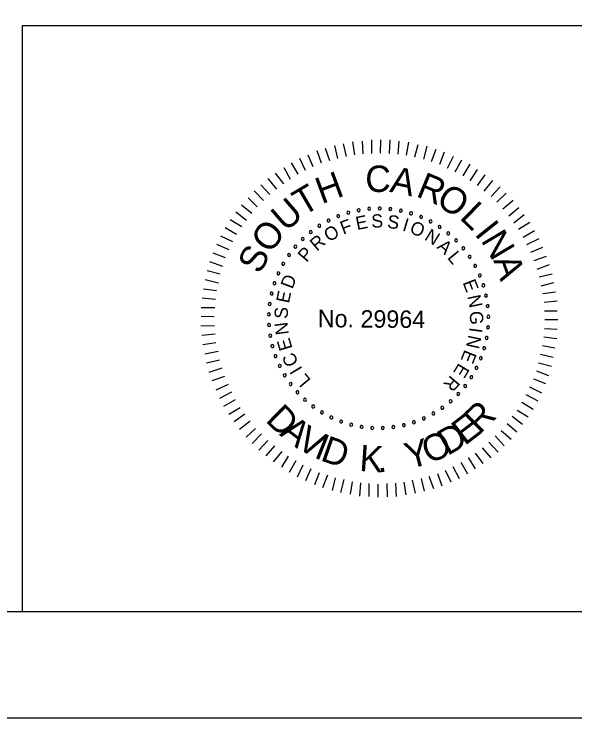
# Model space of a CAD drawing. Extents: x -50.5 to -14.4, y -5.1 to 16.9.
# Drawn here: x -27.924 to -25.289, y -5.066 to -1.762 of the extents above; entities that cross this region are included whole.
import ezdxf

# ---------------------------------------------------------------- set-up
doc = ezdxf.new("R2010")
doc.units = 0
for name, color, linetype in [('BR_BORDER LINES', 7, 'Continuous'), ('BR_TEXT', 7, 'Continuous'), ('Level 31', 7, 'Continuous')]:
    doc.layers.add(name, color=color, linetype=linetype)

msp = doc.modelspace()

# ---------------------------------------------------------------- linework, layer by layer
at = {"layer": 'BR_BORDER LINES'}
for p, q in [((-27.8847, -1.8161), (-22.5195, -1.8161)), ((-27.8847, -4.5661), (-27.8847, -1.8161)), ((-48.6853, -4.5662), (-15.0192, -4.5662))]:
    msp.add_line(p, q, dxfattribs=at)
at = {"layer": 'BR_TEXT'}
for p, q in [((-26.3625, -2.4304), (-26.3767, -2.3711)), ((-26.323, -2.423), (-26.332, -2.362)), ((-26.2835, -2.419), (-26.2873, -2.3581)), ((-26.244, -2.4168), (-26.2435, -2.3524)), ((-26.202, -2.4146), (-26.2015, -2.3528)), ((-26.1599, -2.4175), (-26.1577, -2.3531)), ((-26.1196, -2.4204), (-26.1148, -2.3595)), ((-26.081, -2.425), (-26.0702, -2.3642)), ((-26.0408, -2.4331), (-26.0265, -2.374)), ((-26.4796, -2.4629), (-26.5005, -2.4044)), ((-26.44, -2.4504), (-26.4618, -2.3927)), ((-26.4038, -2.4404), (-26.4171, -2.3793)), ((-25.9997, -2.4437), (-25.9837, -2.3829)), ((-25.9629, -2.4543), (-25.9409, -2.397)), ((-25.9235, -2.4675), (-25.9015, -2.4093)), ((-26.5553, -2.4966), (-26.5815, -2.4406)), ((-26.5183, -2.4798), (-26.5419, -2.4238)), ((-25.8876, -2.485), (-25.8597, -2.4294)), ((-26.5898, -2.5144), (-26.6202, -2.46)), ((-25.8517, -2.5024), (-25.8203, -2.4469)), ((-25.8141, -2.5208), (-25.7819, -2.467)), ((-26.6562, -2.5593), (-26.6953, -2.5083)), ((-26.6252, -2.5381), (-26.6556, -2.4838)), ((-25.7808, -2.5451), (-25.7469, -2.4913)), ((-26.6899, -2.5847), (-26.7299, -2.5346)), ((-25.7475, -2.5668), (-25.711, -2.5165)), ((-25.7151, -2.5928), (-25.6744, -2.5434)), ((-26.7228, -2.6094), (-26.7644, -2.5644)), ((-25.6836, -2.618), (-25.6403, -2.5737)), ((-26.7522, -2.6366), (-26.7964, -2.5925)), ((-25.6555, -2.6456), (-25.6122, -2.6022)), ((-26.7816, -2.6673), (-26.825, -2.6248)), ((-25.6274, -2.6768), (-25.5799, -2.6351)), ((-26.8068, -2.6988), (-26.8562, -2.6598)), ((-25.6002, -2.7088), (-25.5536, -2.6705)), ((-26.8328, -2.732), (-26.8822, -2.6922)), ((-25.5765, -2.7424), (-25.5272, -2.7033)), ((-26.8545, -2.761), (-26.9083, -2.728)), ((-25.5544, -2.7718), (-25.5018, -2.7396)), ((-26.8788, -2.7977), (-26.9326, -2.7656)), ((-26.8963, -2.8319), (-26.9526, -2.804)), ((-25.5324, -2.8089), (-25.4789, -2.7776)), ((-25.5147, -2.8433), (-25.4569, -2.8164)), ((-26.9137, -2.8687), (-26.971, -2.8433)), ((-25.4969, -2.8804), (-25.4401, -2.856)), ((-26.9312, -2.9072), (-26.9894, -2.8852)), ((-25.4801, -2.9192), (-25.4233, -2.8982)), ((-26.9435, -2.9474), (-27.0051, -2.9246)), ((-25.4667, -2.9596), (-25.409, -2.9378)), ((-26.9558, -2.9833), (-27.0167, -2.9682)), ((-25.4567, -2.9957), (-25.3965, -2.9816)), ((-26.9631, -3.0253), (-27.0256, -3.0094)), ((-25.4485, -3.0378), (-25.3882, -3.0229)), ((-26.9736, -3.0613), (-27.0345, -3.0531)), ((-25.4402, -3.074), (-25.3809, -3.0667)), ((-26.9783, -3.1024), (-27.04, -3.0951)), ((-25.4337, -3.1152), (-25.3727, -3.1088)), ((-26.9812, -3.1419), (-27.0455, -3.1414)), ((-25.4323, -3.1547), (-25.3722, -3.1552)), ((-26.9833, -3.183), (-27.0459, -3.1825)), ((-25.43, -3.1959), (-25.3691, -3.1964)), ((-26.9819, -3.226), (-27.0462, -3.2272)), ((-26.9796, -3.2646), (-27.0415, -3.2718)), ((-25.433, -3.2388), (-25.3729, -3.241)), ((-25.435, -3.2774), (-25.3741, -3.2856)), ((-26.9757, -3.3058), (-27.0367, -3.3148)), ((-25.4422, -3.3185), (-25.3831, -3.3284)), ((-26.9657, -3.3454), (-27.0284, -3.3586)), ((-25.4511, -3.3579), (-25.3911, -3.3721)), ((-26.9592, -3.3875), (-27.0202, -3.4016)), ((-25.46, -3.3999), (-25.4001, -3.415)), ((-26.9475, -3.4245), (-27.0094, -3.4454)), ((-26.9358, -3.4632), (-26.9943, -3.4842)), ((-25.4706, -3.4367), (-25.4133, -3.4586)), ((-26.9189, -3.5003), (-26.9766, -3.5272)), ((-25.4847, -3.4752), (-25.4282, -3.4971)), ((-25.5022, -3.512), (-25.4457, -3.5399)), ((-26.9021, -3.5364), (-26.9589, -3.566)), ((-25.5205, -3.5479), (-25.4632, -3.5784)), ((-26.8852, -3.5735), (-26.9395, -3.6048)), ((-25.5388, -3.5846), (-25.4859, -3.6168)), ((-26.8615, -3.6106), (-26.9158, -3.6419)), ((-25.5614, -3.6213), (-25.5093, -3.6535)), ((-26.8403, -3.6399), (-26.8903, -3.6764)), ((-25.584, -3.6503), (-25.5353, -3.6876)), ((-26.8148, -3.6736), (-26.8649, -3.7127)), ((-25.6083, -3.6836), (-25.5623, -3.7234)), ((-26.7902, -3.7073), (-26.8343, -3.7481)), ((-26.7612, -3.7333), (-26.8062, -3.7784)), ((-25.636, -3.7168), (-25.5891, -3.7584)), ((-26.7323, -3.7636), (-26.7747, -3.8095)), ((-25.6645, -3.7424), (-25.622, -3.7882)), ((-26.6999, -3.7895), (-26.7406, -3.8364)), ((-25.7251, -3.7976), (-25.6851, -3.8452)), ((-25.6931, -3.7721), (-25.6506, -3.8188)), ((-26.6666, -3.8156), (-26.7065, -3.8633)), ((-25.7579, -3.8231), (-25.7222, -3.8714)), ((-26.6359, -3.8373), (-26.6672, -3.8894)), ((-26.6009, -3.8599), (-26.6322, -3.9137)), ((-25.7915, -3.8443), (-25.7585, -3.8969)), ((-26.5668, -3.8799), (-26.5938, -3.9355)), ((-26.53, -3.8974), (-26.5545, -3.953)), ((-25.8631, -3.8857), (-25.8327, -3.9418)), ((-25.8252, -3.8663), (-25.7939, -3.9206)), ((-26.4915, -3.9149), (-26.5134, -3.9713)), ((-26.4522, -3.9272), (-26.475, -3.9854)), ((-25.9751, -3.9311), (-25.9541, -3.9897)), ((-25.9355, -3.9194), (-25.9145, -3.9763)), ((-25.8993, -3.9026), (-25.8723, -3.9586)), ((-26.4162, -3.9395), (-26.4304, -3.9986)), ((-26.3751, -3.9467), (-26.3902, -4.0084)), ((-26.3357, -3.9582), (-26.3456, -4.0165)), ((-26.2963, -3.9628), (-26.3011, -4.0246)), ((-26.1324, -3.9642), (-26.1286, -4.026)), ((-26.0937, -3.9602), (-26.0839, -4.0186)), ((-26.0533, -3.9494), (-26.0401, -4.0113)), ((-26.0121, -3.9429), (-25.9971, -4.0022)), ((-26.2568, -3.9657), (-26.2573, -4.0275)), ((-26.2148, -3.9686), (-26.2153, -4.0296)), ((-26.1727, -3.9664), (-26.1715, -4.0282))]:
    msp.add_line(p, q, dxfattribs=at)
for centre, start, end in [((-26.256, -2.6764), 5.0653, 185.0653), ((-26.256, -2.6764), 185.0653, 5.0653), ((-26.2062, -2.6745), 359.5268, 179.5268), ((-26.2062, -2.6745), 179.5268, 359.5268), ((-26.1565, -2.6774), 353.9884, 173.9884), ((-26.4011, -2.7106), 21.6807, 201.6807), ((-26.4011, -2.7106), 201.6807, 21.6807), ((-26.3539, -2.6945), 16.1422, 196.1422), ((-26.3539, -2.6945), 196.1422, 16.1422), ((-26.3054, -2.6831), 10.6038, 190.6038), ((-26.3054, -2.6831), 190.6038, 10.6038), ((-26.1565, -2.6774), 173.9884, 353.9884), ((-26.1073, -2.6851), 168.4499, 348.4499), ((-26.1073, -2.6851), 348.4499, 168.4499), ((-26.059, -2.6976), 162.9114, 342.9114), ((-26.059, -2.6976), 342.9114, 162.9114), ((-26.0122, -2.7146), 337.373, 157.373), ((-26.4465, -2.7311), 27.2191, 207.2191), ((-26.4465, -2.7311), 207.2191, 27.2191), ((-26.0122, -2.7146), 157.373, 337.373), ((-25.9672, -2.736), 151.8345, 331.8345), ((-25.9672, -2.736), 331.8345, 151.8345), ((-26.4897, -2.7559), 32.7576, 212.7576), ((-26.4897, -2.7559), 212.7576, 32.7576), ((-25.9245, -2.7617), 146.2961, 326.2961), ((-25.9245, -2.7617), 326.2961, 146.2961), ((-26.5303, -2.7848), 38.2961, 218.2961), ((-26.5303, -2.7848), 218.2961, 38.2961), ((-25.8845, -2.7914), 140.7576, 320.7576), ((-25.8845, -2.7914), 320.7576, 140.7576), ((-26.568, -2.8175), 43.8345, 223.8345), ((-26.568, -2.8175), 223.8345, 43.8345), ((-25.8475, -2.8249), 135.2191, 315.2191), ((-25.8475, -2.8249), 315.2191, 135.2191), ((-26.6023, -2.8536), 49.373, 229.373), ((-26.6023, -2.8536), 229.373, 49.373), ((-25.814, -2.8617), 129.6807, 309.6807), ((-25.814, -2.8617), 309.6807, 129.6807), ((-26.6329, -2.8929), 54.9114, 234.9114), ((-26.6329, -2.8929), 234.9114, 54.9114), ((-25.7841, -2.9016), 124.1422, 304.1422), ((-25.7841, -2.9016), 304.1422, 124.1422), ((-26.6596, -2.935), 60.4499, 240.4499), ((-26.6596, -2.935), 240.4499, 60.4499), ((-25.7583, -2.9442), 118.6038, 298.6038), ((-25.7583, -2.9442), 298.6038, 118.6038), ((-26.6822, -2.9794), 65.9884, 245.9884), ((-26.6822, -2.9794), 245.9884, 65.9884), ((-25.7366, -2.9891), 113.0653, 293.0653), ((-25.7366, -2.9891), 293.0653, 113.0653), ((-26.7003, -3.0258), 71.5268, 251.5268), ((-26.7003, -3.0258), 251.5268, 71.5268), ((-25.7195, -3.0359), 107.5268, 287.5268), ((-25.7195, -3.0359), 287.5268, 107.5268), ((-26.7139, -3.0738), 77.0653, 257.0653), ((-26.7139, -3.0738), 257.0653, 77.0653), ((-25.7069, -3.0841), 101.9884, 281.9884), ((-25.7069, -3.0841), 281.9884, 101.9884), ((-26.7228, -3.1228), 82.6038, 262.6038), ((-26.7228, -3.1228), 262.6038, 82.6038), ((-25.699, -3.1333), 96.4499, 276.4499), ((-25.699, -3.1333), 276.4499, 96.4499), ((-26.7269, -3.1724), 88.1422, 268.1422), ((-26.7269, -3.1724), 268.1422, 88.1422), ((-25.6959, -3.183), 90.9114, 270.9114), ((-25.6959, -3.183), 270.9114, 90.9114), ((-26.7262, -3.2223), 93.6807, 273.6807), ((-26.7262, -3.2223), 273.6807, 93.6807), ((-25.6976, -3.2328), 85.373, 265.373), ((-25.6976, -3.2328), 265.373, 85.373), ((-26.7207, -3.2718), 99.2191, 279.2191), ((-26.7207, -3.2718), 279.2191, 99.2191), ((-25.7041, -3.2822), 79.8345, 259.8345), ((-25.7041, -3.2822), 259.8345, 79.8345), ((-26.7105, -3.3206), 104.7576, 284.7576), ((-26.7105, -3.3206), 284.7576, 104.7576), ((-25.7154, -3.3308), 74.2961, 254.2961), ((-25.7154, -3.3308), 254.2961, 74.2961), ((-26.6956, -3.3681), 110.2961, 290.2961), ((-26.6956, -3.3681), 290.2961, 110.2961), ((-25.7312, -3.378), 68.7576, 248.7576), ((-25.7312, -3.378), 248.7576, 68.7576), ((-26.6761, -3.414), 115.8345, 295.8345), ((-26.6761, -3.414), 295.8345, 115.8345), ((-25.7516, -3.4235), 63.2191, 243.2191), ((-25.7516, -3.4235), 243.2191, 63.2191), ((-26.6524, -3.4578), 121.373, 301.373), ((-26.6524, -3.4578), 301.373, 121.373), ((-25.7763, -3.4668), 57.6807, 237.6807), ((-25.7763, -3.4668), 237.6807, 57.6807), ((-26.6245, -3.4991), 126.9114, 306.9114), ((-26.6245, -3.4991), 306.9114, 126.9114), ((-25.805, -3.5075), 52.1422, 232.1422), ((-25.805, -3.5075), 232.1422, 52.1422), ((-26.5927, -3.5375), 132.4499, 312.4499), ((-26.5927, -3.5375), 312.4499, 132.4499), ((-26.5574, -3.5727), 137.9884, 317.9884), ((-26.5574, -3.5727), 317.9884, 137.9884), ((-25.8375, -3.5452), 46.6038, 226.6038), ((-25.8375, -3.5452), 226.6038, 46.6038), ((-26.5189, -3.6043), 143.5268, 323.5268), ((-26.5189, -3.6043), 323.5268, 143.5268), ((-25.8735, -3.5797), 41.0653, 221.0653), ((-25.8735, -3.5797), 221.0653, 41.0653), ((-26.4775, -3.632), 149.0653, 329.0653), ((-26.4775, -3.632), 329.0653, 149.0653), ((-25.9547, -3.6374), 29.9884, 209.9884), ((-25.9547, -3.6374), 209.9884, 29.9884), ((-25.9127, -3.6105), 35.5268, 215.5268), ((-25.9127, -3.6105), 215.5268, 35.5268), ((-26.4336, -3.6556), 154.6038, 334.6038), ((-26.4336, -3.6556), 334.6038, 154.6038), ((-25.999, -3.6601), 24.4499, 204.4499), ((-25.999, -3.6601), 204.4499, 24.4499), ((-26.3877, -3.6749), 160.1422, 340.1422), ((-26.3877, -3.6749), 340.1422, 160.1422), ((-26.3401, -3.6896), 165.6807, 345.6807), ((-26.3401, -3.6896), 345.6807, 165.6807), ((-26.2913, -3.6997), 171.2191, 351.2191), ((-26.2913, -3.6997), 351.2191, 171.2191), ((-26.2417, -3.705), 356.7576, 176.7576), ((-26.1919, -3.7055), 2.2961, 182.2961), ((-26.1422, -3.7012), 7.8345, 187.8345), ((-26.1422, -3.7012), 187.8345, 7.8345), ((-26.0932, -3.6921), 13.373, 193.373), ((-26.0932, -3.6921), 193.373, 13.373), ((-26.0454, -3.6784), 18.9114, 198.9114), ((-26.0454, -3.6784), 198.9114, 18.9114), ((-26.2417, -3.705), 176.7576, 356.7576), ((-26.1919, -3.7055), 182.2961, 2.2961)]:
    msp.add_arc(centre, 0.00701, start, end, dxfattribs=at)
at = {"layer": 'Level 31'}
msp.add_lwpolyline([(-50.5186, -5.0661), (-14.5186, -5.0661), (-14.5186, 16.9339), (-50.5186, 16.9339)], close=True, dxfattribs=at)

# ---------------------------------------------------------------- texts
at = {"layer": 'BR_TEXT'}
for s, height, rotation, p in [('C', 0.1241, 359.5482, (-26.2747, -2.5969)), ('H', 0.1241, 20.3637, (-26.4791, -2.6552)), ('A', 0.1241, 348.1981, (-26.1633, -2.5961)), ('R', 0.1241, 337.4344, (-26.0401, -2.616)), ('T', 0.1241, 30.4992, (-26.567, -2.7128)), ('O', 0.1239, 326.5869, (-25.9478, -2.6528)), ('U', 0.1241, 40.8022, (-26.6482, -2.7875)), ('L', 0.1241, 315.9488, (-25.8352, -2.7205)), ('E', 0.0622, 11.4103, (-26.3127, -2.7764)), ('S', 0.0622, 2.208, (-26.2449, -2.7654)), ('S', 0.0622, 352.6608, (-26.1736, -2.7657)), ('O', 0.1241, 52.0267, (-26.7228, -2.8914)), ('F', 0.0622, 20.6127, (-26.3779, -2.7981)), ('I', 0.0622, 343.1136, (-26.1034, -2.7777)), ('O', 0.0622, 338.4392, (-26.07, -2.7878)), ('I', 0.1241, 308.6613, (-25.7639, -2.7948)), ('O', 0.0622, 30.8477, (-26.4452, -2.8341)), ('N', 0.0622, 328.2042, (-26.0003, -2.8192)), ('N', 0.1241, 300.7037, (-25.7333, -2.8242)), ('R', 0.0622, 40.3949, (-26.5014, -2.878)), ('A', 0.0622, 318.657, (-25.9414, -2.8592)), ('S', 0.1239, 63.2511, (-26.7681, -2.9871)), ('P', 0.0622, 49.9421, (-26.5495, -2.9306)), ('L', 0.0622, 309.4546, (-25.8916, -2.9066)), ('A', 0.1241, 289.4792, (-25.6741, -2.9172)), ('D', 0.0622, 69.0364, (-26.6164, -3.0559)), ('E', 0.0622, 291.049, (-25.8177, -3.0219)), ('E', 0.0622, 78.2388, (-26.633, -3.1226)), ('N', 0.0622, 281.8466, (-25.7955, -3.0869)), ('S', 0.0622, 87.786, (-26.6387, -3.1936)), ('No. 29964', 0.08175, 359.5268, (-26.4976, -3.232)), ('G', 0.0622, 272.2995, (-25.7838, -3.1572)), ('N', 0.0622, 97.3332, (-26.6325, -3.2646)), ('I', 0.0622, 262.4084, (-25.7841, -3.231)), ('E', 0.0622, 106.5355, (-26.6155, -3.3312)), ('N', 0.0622, 257.7339, (-25.7887, -3.2656)), ('C', 0.0622, 116.4266, (-26.5857, -3.3987)), ('E', 0.0622, 248.1867, (-25.8067, -3.3346)), ('I', 0.0622, 121.1011, (-26.5676, -3.4285)), ('E', 0.0622, 238.9844, (-25.8347, -3.3973)), ('L', 0.0622, 129.9595, (-26.5269, -3.4807)), ('R', 0.0622, 229.782, (-25.8723, -3.4548)), ('D', 0.1236, 315.4053, (-26.7474, -3.6713)), ('R', 0.1236, 44.5947, (-25.7366, -3.7369)), ('E', 0.1236, 37.5339, (-25.8072, -3.7908)), ('A', 0.1236, 322.8377, (-26.6808, -3.737)), ('V', 0.1236, 330.5179, (-26.6037, -3.7952)), ('D', 0.1236, 30.1015, (-25.8881, -3.8377)), ('O', 0.1236, 22.4212, (-25.9773, -3.8748)), ('I', 0.1236, 338.1981, (-26.5195, -3.8425)), ('D', 0.1236, 340.7995, (-26.4896, -3.856)), ('Y', 0.1236, 14.8649, (-26.0692, -3.8993)), ('K', 0.1236, 356.098, (-26.3043, -3.9065)), ('.', 0.1236, 3.1588, (-26.2157, -3.9128))]:
    msp.add_text(s, height=height, rotation=rotation, dxfattribs=at).set_placement(p)

doc.saveas('drawing.dxf')
